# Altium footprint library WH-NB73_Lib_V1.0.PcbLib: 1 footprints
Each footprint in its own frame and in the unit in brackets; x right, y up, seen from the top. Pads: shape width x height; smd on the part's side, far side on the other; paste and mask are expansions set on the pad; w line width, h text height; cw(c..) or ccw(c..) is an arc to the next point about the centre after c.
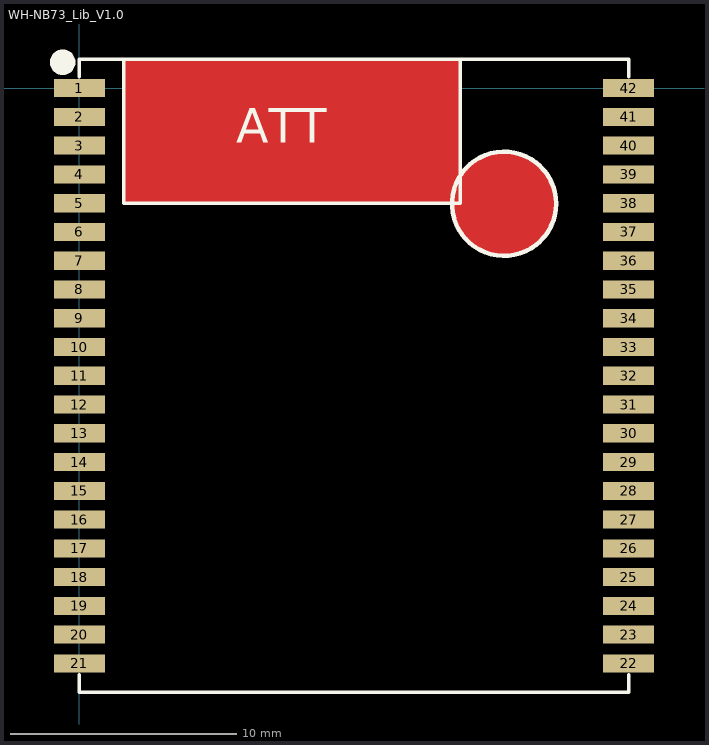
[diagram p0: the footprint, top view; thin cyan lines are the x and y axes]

## WH-NB73_Lib_V1.0 [mm]
pads (42):
  rect 2.25x0.8 smd: 1(0,0) 2(0,-1.27) 3(0,-2.54) 4(0,-3.81) 5(0,-5.08) 6(0,-6.35) 7(0,-7.62) 8(0,-8.89) 9(0,-10.16) 10(0,-11.43) 11(0,-12.7) 12(0,-13.97) 13(0,-15.24) 14(0,-16.51) 15(0,-17.78) 16(0,-19.05) 17(0,-20.32) 18(0,-21.59) 19(0,-22.86) 20(0,-24.13) 21(0,-25.4) 22(24.25,-25.4) 23(24.25,-24.13) 24(24.25,-22.86) 25(24.25,-21.59) 26(24.25,-20.32) 27(24.25,-19.05) 28(24.25,-17.78) 29(24.25,-16.51) 30(24.25,-15.24) 31(24.25,-13.97) 32(24.25,-12.7) 33(24.25,-11.43) 34(24.25,-10.16) 35(24.25,-8.89) 36(24.25,-7.62) 37(24.25,-6.35) 38(24.25,-5.08) 39(24.25,-3.81) 40(24.25,-2.54) 41(24.25,-1.27) 42(24.25,0)
Top Layer:
  pour cut-out: 1.965,-5.08 1.965,1.27 16.824,1.27 16.824,-5.08
  pour cut-out: 21.061,-5.105 21.017,-4.653 20.885,-4.219 20.671,-3.818 20.383,-3.467 20.032,-3.179 19.631,-2.965 19.197,-2.833 18.745,-2.789 18.745,-2.8 18.7,-2.789 18.26,-2.832 17.836,-2.961 17.446,-3.169 17.104,-3.45 16.823,-3.792 16.615,-4.182 16.486,-4.606 16.443,-5.046 16.454,-5.046 16.443,-5.1 16.488,-5.555 16.62,-5.992 16.836,-6.395 17.126,-6.748 17.479,-7.038 17.882,-7.254 18.319,-7.386 18.774,-7.431 18.774,-7.42 18.79,-7.431 19.233,-7.387 19.659,-7.258 20.052,-7.048 20.396,-6.766 20.678,-6.422 20.888,-6.029 21.017,-5.603 21.061,-5.16 21.05,-5.16
Top Overlay:
  circle w0.559: c-0.737,1.143 r0.284
  circle w0.2: c18.75,-5.105 r2.3
  lines w0.152: 0,-25.908 0,-26.67 24.25,-26.67 24.25,-25.908 ; 0,0.508 0,1.27 24.25,1.27 24.25,0.508 ; 1.965,-1.27 1.965,-5.08 13.838,-5.08 16.824,-5.08 16.824,-3.81 16.824,1.27 ; 1.965,-1.238 1.965,1.27
  text "ATT" at 6.918,-2.413 h1.52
